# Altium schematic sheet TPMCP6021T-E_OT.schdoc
size 127 x 101 mm
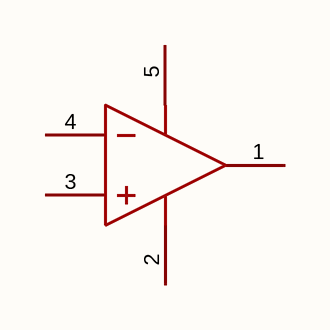
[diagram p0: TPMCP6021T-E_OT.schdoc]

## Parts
U?  tpmcp6021t-e/ot  [SOT-23-5_L3.0-W1.7-P0.95-LS2.8-BR]  (value not drawn)

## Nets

Not connected (* = marked no-connect by the designer): U? 1(OUT) 2(V-) 3(+IN) 4(-IN) 5(V+)

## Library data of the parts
U? = tpmcp6021t-e/ot: 放大器数:1;轨到轨:轨到轨输入,轨到轨输出;增益带宽积(GBW):10MHz;输入失调电压(Vos):5mV;压摆率(SR):4.5V/us;输入偏置电流(Ib):1pA;; Manufacturer: TECH PUBLIC(台舟); AddInBom: yes; ModelId: 0a2a1b8f50944f73965918ad6e5fe167; ModelName: SOT-23-5_L2.9-W1.6-H1.1-LS2.8-P0.95; ModelTransform: 114.173,109.636,0,180,0,0,0,0,0; Number of Channels: 1; Maximum Power Supply Range (Vdd-Vss): 5.5V; Gain Bandwidth Product: 10MHz; Vos - Input Offset Voltage: 5mV; Input Offset Voltage Drift(Vos TC): 6uV/℃; Ib - Input Bias Current: 1pA; Input Offset Current(Ios): 100pA; Input Voltage Noise Density: 15nV/√Hz@30kHz; Common Mode Rejection Ratio(CMRR): 75dB; Quiescent Current: 800uA; Output Current: 50mA; Single supply: 2.2V~5.5V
